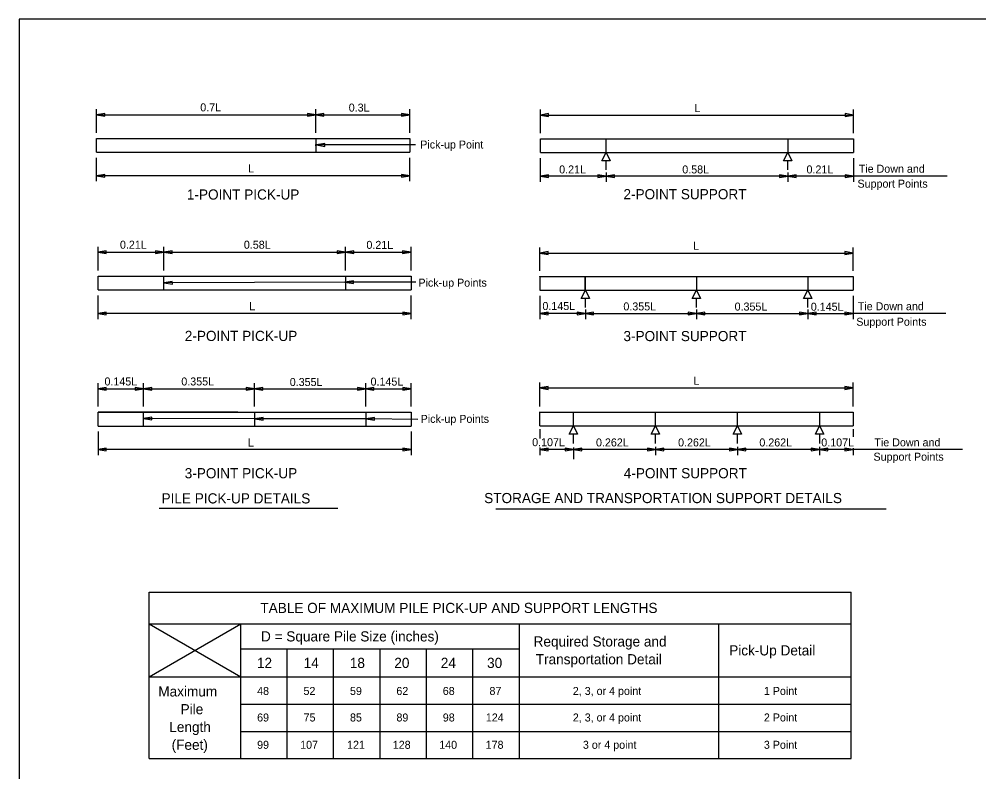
# Model space of a CAD drawing. Extents: x 112309.5 to 112344.2, y 111905.2 to 111923.
# Drawn here: x 112309.53 to 112321.62, y 111912.5 to 111921.98 of the extents above; entities that cross this region are included whole.
import ezdxf

# ---------------------------------------------------------------- set-up
doc = ezdxf.new("R2010")
doc.units = 0
for name, color, linetype in [('ActivePts-ConstElements', 7, 'Continuous'), ('AdhocPoint_dp', 7, 'Continuous'), ('PlotBorder_dp', 7, 'Continuous'), ('TextMisc', 7, 'Continuous')]:
    doc.layers.add(name, color=color, linetype=linetype)

msp = doc.modelspace()

# ---------------------------------------------------------------- linework, layer by layer
at = {"layer": 'ActivePts-ConstElements'}
msp.add_lwpolyline([(112309.535, 111909.004), (112330.06, 111909.004), (112330.06, 111921.977), (112309.535, 111921.977)], close=True, dxfattribs=at)
at = {"layer": 'AdhocPoint_dp'}
for p, q in [((112310.509, 111920.544), (112310.509, 111920.844)), ((112313.27, 111920.544), (112313.27, 111920.844)), ((112314.454, 111920.544), (112314.454, 111920.844)), ((112316.1, 111920.542), (112316.1, 111920.839)), ((112320.045, 111920.542), (112320.045, 111920.839)), ((112310.509, 111920.774), (112313.27, 111920.774)), ((112313.27, 111920.774), (112314.454, 111920.774)), ((112316.1, 111920.769), (112320.045, 111920.769)), ((112314.529, 111920.393), (112313.279, 111920.393)), ((112310.509, 111919.935), (112310.509, 111920.229)), ((112314.454, 111919.935), (112314.454, 111920.23)), ((112316.1, 111919.93), (112316.1, 111920.228)), ((112316.929, 111920.078), (112316.929, 111920.194)), ((112319.218, 111920.078), (112319.218, 111920.194)), ((112320.045, 111920.228), (112320.045, 111919.93)), ((112314.454, 111920.005), (112310.509, 111920.005)), ((112316.929, 111920), (112316.1, 111920)), ((112316.929, 111920.045), (112316.929, 111919.93)), ((112319.217, 111920), (112316.929, 111920)), ((112319.217, 111920.044), (112319.217, 111919.93)), ((112320.045, 111920), (112319.217, 111920)), ((112321.226, 111920), (112320.045, 111920)), ((112310.528, 111918.812), (112310.528, 111919.111)), ((112311.356, 111918.812), (112311.356, 111919.111)), ((112313.644, 111918.812), (112313.644, 111919.111)), ((112314.473, 111918.812), (112314.473, 111919.111)), ((112316.095, 111918.808), (112316.095, 111919.102)), ((112320.039, 111918.808), (112320.039, 111919.102)), ((112310.528, 111919.041), (112311.356, 111919.041)), ((112311.356, 111919.041), (112313.644, 111919.041)), ((112313.644, 111919.041), (112314.469, 111919.041)), ((112316.095, 111919.032), (112320.039, 111919.032)), ((112316.095, 111918.738), (112316.095, 111918.742)), ((112316.666, 111918.738), (112316.666, 111918.74)), ((112318.067, 111918.738), (112318.067, 111918.741)), ((112313.639, 111918.665), (112311.359, 111918.657)), ((112314.532, 111918.665), (112313.639, 111918.665)), ((112310.528, 111918.2), (112310.528, 111918.497)), ((112314.473, 111918.2), (112314.473, 111918.497)), ((112316.095, 111918.494), (112316.095, 111918.2)), ((112320.039, 111918.494), (112320.039, 111918.2)), ((112316.668, 111918.344), (112316.668, 111918.46)), ((112318.068, 111918.344), (112318.068, 111918.46)), ((112319.469, 111918.344), (112319.469, 111918.46)), ((112314.473, 111918.27), (112310.528, 111918.27)), ((112316.667, 111918.27), (112316.095, 111918.27)), ((112316.667, 111918.321), (112316.667, 111918.2)), ((112316.667, 111918.27), (112318.069, 111918.27)), ((112318.069, 111918.321), (112318.069, 111918.2)), ((112318.069, 111918.27), (112319.469, 111918.27)), ((112319.469, 111918.321), (112319.469, 111918.2)), ((112319.469, 111918.27), (112320.039, 111918.27)), ((112321.206, 111918.27), (112320.039, 111918.27)), ((112316.095, 111917.099), (112316.095, 111917.403)), ((112320.039, 111917.099), (112320.039, 111917.403)), ((112310.528, 111917.097), (112310.528, 111917.392)), ((112310.528, 111917.322), (112311.099, 111917.322)), ((112311.099, 111917.097), (112311.099, 111917.392)), ((112311.099, 111917.322), (112312.5, 111917.322)), ((112312.5, 111917.097), (112312.5, 111917.392)), ((112312.5, 111917.322), (112313.9, 111917.322)), ((112313.9, 111917.097), (112313.9, 111917.392)), ((112313.9, 111917.322), (112314.473, 111917.322)), ((112314.473, 111917.097), (112314.473, 111917.392)), ((112316.095, 111917.333), (112320.039, 111917.333)), ((112316.095, 111917.029), (112316.095, 111917.033)), ((112312.504, 111916.945), (112311.1, 111916.948)), ((112313.907, 111916.945), (112312.504, 111916.945)), ((112314.556, 111916.936), (112313.907, 111916.945)), ((112316.666, 111917.029), (112316.666, 111917.031)), ((112318.067, 111917.029), (112318.067, 111917.032)), ((112316.095, 111916.815), (112316.095, 111916.695)), ((112320.039, 111916.815), (112320.039, 111916.716)), ((112310.528, 111916.783), (112310.528, 111916.487)), ((112314.473, 111916.783), (112314.473, 111916.487)), ((112316.518, 111916.635), (112316.518, 111916.751)), ((112317.551, 111916.635), (112317.551, 111916.751)), ((112318.584, 111916.635), (112318.584, 111916.751)), ((112319.619, 111916.635), (112319.619, 111916.751)), ((112314.473, 111916.557), (112310.528, 111916.557)), ((112316.095, 111916.583), (112316.095, 111916.487)), ((112316.518, 111916.557), (112316.095, 111916.557)), ((112316.517, 111916.584), (112316.517, 111916.437)), ((112317.552, 111916.557), (112316.518, 111916.557)), ((112317.55, 111916.591), (112317.55, 111916.487)), ((112318.585, 111916.557), (112317.552, 111916.557)), ((112318.584, 111916.591), (112318.584, 111916.487)), ((112319.617, 111916.557), (112318.585, 111916.557)), ((112319.617, 111916.59), (112319.617, 111916.487)), ((112320.038, 111916.557), (112319.617, 111916.557)), ((112321.418, 111916.557), (112320.038, 111916.557)), ((112320.039, 111916.576), (112320.039, 111916.487)), ((112316.517, 111916.519), (112316.517, 111916.487)), ((112318.585, 111916.487), (112318.585, 111916.487)), ((112313.55, 111915.814), (112311.298, 111915.814)), ((112315.539, 111915.811), (112320.458, 111915.811)), ((112311.172, 111912.666), (112311.172, 111914.762)), ((112311.172, 111914.762), (112320.016, 111914.762)), ((112320.016, 111912.666), (112320.016, 111914.762)), ((112311.172, 111914.362), (112320.016, 111914.362)), ((112311.172, 111913.695), (112312.327, 111914.362)), ((112311.172, 111914.362), (112312.327, 111913.695)), ((112312.327, 111912.666), (112312.327, 111914.362)), ((112315.836, 111912.666), (112315.836, 111914.362)), ((112318.349, 111912.666), (112318.349, 111914.362)), ((112312.327, 111914.045), (112315.836, 111914.045)), ((112312.911, 111912.666), (112312.911, 111914.045)), ((112313.496, 111912.666), (112313.496, 111914.045)), ((112314.081, 111912.666), (112314.081, 111914.045)), ((112314.666, 111912.666), (112314.666, 111914.045)), ((112315.251, 111912.666), (112315.251, 111914.045)), ((112311.172, 111913.695), (112320.016, 111913.695)), ((112312.327, 111913.35), (112320.016, 111913.35)), ((112312.327, 111913.005), (112320.016, 111913.005)), ((112311.172, 111912.666), (112320.016, 111912.666))]:
    msp.add_line(p, q, dxfattribs=at)
for points in [[(112310.509, 111920.774), (112310.614, 111920.756), (112310.614, 111920.791)], [(112313.27, 111920.774), (112313.166, 111920.791), (112313.166, 111920.756)], [(112313.27, 111920.774), (112313.374, 111920.756), (112313.374, 111920.791)], [(112314.454, 111920.774), (112314.35, 111920.791), (112314.35, 111920.756)], [(112316.1, 111920.769), (112316.204, 111920.751), (112316.204, 111920.787)], [(112320.045, 111920.769), (112319.941, 111920.787), (112319.941, 111920.751)], [(112313.264, 111920.392), (112313.282, 111920.389), (112313.282, 111920.395)], [(112313.279, 111920.393), (112313.383, 111920.375), (112313.383, 111920.411)], [(112316.929, 111920.298), (112316.981, 111920.194), (112316.876, 111920.194)], [(112319.217, 111920.298), (112319.269, 111920.194), (112319.164, 111920.194)], [(112310.509, 111920.005), (112310.614, 111919.987), (112310.614, 111920.022)], [(112314.454, 111920.005), (112314.349, 111920.022), (112314.349, 111919.987)], [(112316.1, 111920), (112316.204, 111919.982), (112316.204, 111920.018)], [(112316.929, 111920), (112316.824, 111920.018), (112316.824, 111919.982)], [(112316.929, 111920), (112317.033, 111919.982), (112317.033, 111920.018)], [(112319.217, 111920), (112319.113, 111920.018), (112319.113, 111919.982)], [(112319.217, 111920), (112319.321, 111919.982), (112319.321, 111920.018)], [(112320.045, 111920), (112319.941, 111920.018), (112319.941, 111919.982)], [(112310.528, 111919.041), (112310.632, 111919.024), (112310.632, 111919.059)], [(112311.356, 111919.041), (112311.252, 111919.059), (112311.252, 111919.024)], [(112311.356, 111919.041), (112311.46, 111919.024), (112311.46, 111919.059)], [(112313.644, 111919.041), (112313.54, 111919.059), (112313.54, 111919.024)], [(112313.644, 111919.041), (112313.749, 111919.024), (112313.749, 111919.059)], [(112314.469, 111919.041), (112314.364, 111919.059), (112314.364, 111919.024)], [(112316.095, 111919.032), (112316.199, 111919.014), (112316.199, 111919.05)], [(112320.039, 111919.032), (112319.935, 111919.05), (112319.935, 111919.014)], [(112311.359, 111918.657), (112311.464, 111918.639), (112311.463, 111918.675)], [(112313.639, 111918.665), (112313.744, 111918.647), (112313.744, 111918.683)], [(112316.667, 111918.564), (112316.719, 111918.46), (112316.614, 111918.46)], [(112318.067, 111918.564), (112318.119, 111918.46), (112318.014, 111918.46)], [(112319.468, 111918.564), (112319.52, 111918.46), (112319.415, 111918.46)], [(112310.528, 111918.27), (112310.632, 111918.252), (112310.632, 111918.287)], [(112314.473, 111918.27), (112314.369, 111918.287), (112314.369, 111918.252)], [(112316.095, 111918.27), (112316.199, 111918.252), (112316.199, 111918.287)], [(112316.667, 111918.27), (112316.563, 111918.287), (112316.563, 111918.252)], [(112316.667, 111918.27), (112316.771, 111918.252), (112316.771, 111918.287)], [(112318.069, 111918.27), (112317.964, 111918.287), (112317.964, 111918.252)], [(112318.069, 111918.27), (112318.173, 111918.252), (112318.173, 111918.287)], [(112319.469, 111918.27), (112319.365, 111918.287), (112319.365, 111918.252)], [(112319.469, 111918.27), (112319.574, 111918.252), (112319.574, 111918.287)], [(112320.039, 111918.27), (112319.935, 111918.287), (112319.935, 111918.252)], [(112310.528, 111917.322), (112310.632, 111917.304), (112310.632, 111917.34)], [(112311.099, 111917.322), (112310.995, 111917.34), (112310.995, 111917.304)], [(112311.099, 111917.322), (112311.204, 111917.304), (112311.204, 111917.34)], [(112312.5, 111917.322), (112312.396, 111917.34), (112312.396, 111917.304)], [(112312.5, 111917.322), (112312.604, 111917.304), (112312.604, 111917.34)], [(112313.9, 111917.322), (112313.796, 111917.34), (112313.796, 111917.304)], [(112313.9, 111917.322), (112314.004, 111917.304), (112314.004, 111917.34)], [(112314.473, 111917.322), (112314.369, 111917.34), (112314.369, 111917.304)], [(112316.095, 111917.333), (112316.199, 111917.315), (112316.199, 111917.35)], [(112320.039, 111917.333), (112319.935, 111917.35), (112319.935, 111917.315)], [(112311.1, 111916.948), (112311.204, 111916.93), (112311.204, 111916.965)], [(112312.504, 111916.945), (112312.608, 111916.927), (112312.608, 111916.962)], [(112313.907, 111916.945), (112314.011, 111916.926), (112314.011, 111916.961)], [(112316.517, 111916.855), (112316.569, 111916.751), (112316.464, 111916.751)], [(112317.55, 111916.855), (112317.603, 111916.751), (112317.498, 111916.751)], [(112318.584, 111916.855), (112318.636, 111916.751), (112318.531, 111916.751)], [(112319.618, 111916.855), (112319.67, 111916.751), (112319.565, 111916.751)], [(112310.528, 111916.557), (112310.632, 111916.539), (112310.632, 111916.574)], [(112314.473, 111916.557), (112314.369, 111916.574), (112314.369, 111916.539)], [(112316.095, 111916.557), (112316.199, 111916.539), (112316.199, 111916.574)], [(112316.518, 111916.557), (112316.414, 111916.574), (112316.414, 111916.539)], [(112316.518, 111916.557), (112316.622, 111916.539), (112316.622, 111916.574)], [(112317.552, 111916.557), (112317.448, 111916.574), (112317.448, 111916.539)], [(112317.552, 111916.557), (112317.656, 111916.539), (112317.656, 111916.574)], [(112318.585, 111916.557), (112318.481, 111916.574), (112318.481, 111916.539)], [(112318.585, 111916.557), (112318.689, 111916.539), (112318.689, 111916.574)], [(112319.617, 111916.557), (112319.513, 111916.574), (112319.513, 111916.539)], [(112319.617, 111916.557), (112319.721, 111916.539), (112319.721, 111916.574)], [(112320.038, 111916.557), (112319.934, 111916.574), (112319.934, 111916.539)]]:
    msp.add_lwpolyline(points, close=True, dxfattribs=at)
at = {"layer": 'PlotBorder_dp'}
for p, q in [((112310.509, 111920.474), (112314.454, 111920.474)), ((112310.509, 111920.3), (112310.509, 111920.474)), ((112313.27, 111920.474), (112313.27, 111920.3)), ((112314.454, 111920.474), (112314.454, 111920.3)), ((112316.1, 111920.472), (112320.045, 111920.472)), ((112316.1, 111920.298), (112316.1, 111920.472)), ((112316.929, 111920.298), (112316.929, 111920.472)), ((112319.217, 111920.472), (112319.217, 111920.298)), ((112320.045, 111920.472), (112320.045, 111920.298)), ((112310.509, 111920.3), (112314.454, 111920.3)), ((112316.1, 111920.298), (112320.045, 111920.298)), ((112310.528, 111918.742), (112314.473, 111918.742)), ((112310.528, 111918.568), (112310.528, 111918.742)), ((112311.356, 111918.568), (112311.356, 111918.742)), ((112313.644, 111918.742), (112313.644, 111918.568)), ((112314.473, 111918.742), (112314.473, 111918.568)), ((112316.095, 111918.738), (112320.039, 111918.738)), ((112316.095, 111918.738), (112316.095, 111918.564)), ((112316.666, 111918.564), (112316.666, 111918.738)), ((112316.667, 111918.564), (112316.667, 111918.738)), ((112318.067, 111918.738), (112318.067, 111918.564)), ((112318.141, 111918.738), (112320.039, 111918.738)), ((112319.468, 111918.738), (112319.468, 111918.564)), ((112320.039, 111918.738), (112320.039, 111918.564)), ((112310.528, 111918.568), (112314.473, 111918.568)), ((112316.095, 111918.564), (112320.039, 111918.564)), ((112310.528, 111917.027), (112314.473, 111917.027)), ((112312.287, 111917.027), (112310.528, 111917.027)), ((112310.528, 111916.853), (112310.528, 111917.027)), ((112311.099, 111916.853), (112311.099, 111917.027)), ((112312.5, 111917.027), (112312.5, 111916.853)), ((112313.9, 111917.027), (112313.9, 111916.853)), ((112314.473, 111917.027), (112314.473, 111916.853)), ((112316.095, 111917.029), (112320.039, 111917.029)), ((112316.095, 111916.855), (112316.095, 111917.029)), ((112316.517, 111916.855), (112316.517, 111917.029)), ((112317.55, 111916.855), (112317.55, 111917.029)), ((112318.141, 111917.029), (112320.039, 111917.029)), ((112318.584, 111916.855), (112318.584, 111917.029)), ((112319.618, 111917.029), (112319.618, 111916.855)), ((112320.039, 111917.029), (112320.039, 111916.855)), ((112310.528, 111916.853), (112314.473, 111916.853)), ((112316.095, 111916.855), (112320.039, 111916.855))]:
    msp.add_line(p, q, dxfattribs=at)

# ---------------------------------------------------------------- texts
at = {"layer": 'AdhocPoint_dp'}
for s, p in [('Required Storage and', (112316.015, 111914.076)), ('Transportation Detail  ', (112316.042, 111913.852)), ('Maximum', (112311.287, 111913.447)), ('Pile', (112311.568, 111913.223)), ('Length', (112311.426, 111912.999)), ('(Feet)', (112311.455, 111912.775))]:
    msp.add_text(s, height=0.128, dxfattribs=at).set_placement(p)
at = {"layer": 'TextMisc'}
for s, height, p in [('0.7L', 0.1008, (112311.816, 111920.816)), ('0.3L', 0.1008, (112313.686, 111920.813)), ('L', 0.101, (112318.04, 111920.807)), ('Pick-up Point', 0.1008, (112314.587, 111920.348)), ('L', 0.101, (112312.418, 111920.047)), ('0.21L', 0.1008, (112316.337, 111920.034)), ('0.58L', 0.1008, (112317.888, 111920.034)), ('0.21L', 0.1008, (112319.453, 111920.034)), ('Tie Down and', 0.1008, (112320.111, 111920.043)), ('Support Points', 0.1008, (112320.095, 111919.855)), ('1-POINT PICK-UP', 0.128, (112311.647, 111919.705)), ('2-POINT SUPPORT', 0.128, (112317.147, 111919.709)), ('0.21L', 0.1008, (112310.804, 111919.086)), ('0.58L', 0.1008, (112312.365, 111919.086)), ('0.21L', 0.1008, (112313.909, 111919.084)), ('L', 0.101, (112318.025, 111919.072)), ('Pick-up Points', 0.1008, (112314.564, 111918.608)), ('L', 0.101, (112312.433, 111918.312)), ('0.145L', 0.1008, (112316.126, 111918.314)), ('0.355L', 0.1008, (112317.146, 111918.309)), ('0.355L', 0.1008, (112318.547, 111918.307)), ('0.145L', 0.1008, (112319.507, 111918.305)), ('Tie Down and', 0.1008, (112320.099, 111918.311)), ('Support Points', 0.1008, (112320.08, 111918.116)), ('2-POINT PICK-UP', 0.128, (112311.621, 111917.924)), ('3-POINT SUPPORT', 0.128, (112317.147, 111917.922)), ('0.145L', 0.1008, (112310.609, 111917.364)), ('0.355L', 0.1008, (112311.577, 111917.364)), ('0.355L', 0.1008, (112312.943, 111917.357)), ('0.145L', 0.1008, (112313.961, 111917.362)), ('L', 0.101, (112318.03, 111917.372)), ('Pick-up Points', 0.1008, (112314.592, 111916.893)), ('L', 0.101, (112312.416, 111916.595)), ('0.107L', 0.1008, (112315.997, 111916.599)), ('0.262L', 0.1008, (112316.801, 111916.596)), ('0.262L', 0.1008, (112317.835, 111916.596)), ('0.262L', 0.1008, (112318.859, 111916.596)), ('0.107L', 0.1008, (112319.639, 111916.596)), ('Tie Down and', 0.1008, (112320.308, 111916.597)), ('Support Points', 0.1008, (112320.297, 111916.416)), ('3-POINT PICK-UP', 0.128, (112311.62, 111916.195)), ('4-POINT SUPPORT', 0.128, (112317.151, 111916.195)), ('PILE PICK-UP DETAILS', 0.128, (112311.328, 111915.878)), ('STORAGE AND TRANSPORTATION SUPPORT DETAILS', 0.128, (112315.392, 111915.882)), ('TABLE OF MAXIMUM PILE PICK-UP AND SUPPORT LENGTHS', 0.128, (112312.573, 111914.498)), ('D = Square Pile Size (inches)', 0.128, (112312.581, 111914.14)), ('Pick-Up Detail', 0.128, (112318.479, 111913.964)), ('12', 0.128, (112312.53, 111913.806)), ('14', 0.128, (112313.118, 111913.806)), ('18', 0.128, (112313.7, 111913.806)), ('20', 0.128, (112314.26, 111913.806)), ('24', 0.128, (112314.846, 111913.806)), ('30', 0.128, (112315.429, 111913.806)), ('48', 0.1008, (112312.532, 111913.466)), ('52', 0.1008, (112313.116, 111913.466)), ('59', 0.1008, (112313.702, 111913.466)), ('62', 0.1008, (112314.286, 111913.466)), ('68', 0.1008, (112314.871, 111913.466)), ('87', 0.1008, (112315.459, 111913.466)), ('2, 3, or 4 point', 0.1008, (112316.509, 111913.466)), ('1 Point', 0.1008, (112318.916, 111913.466)), ('69', 0.1008, (112312.532, 111913.132)), ('75', 0.1008, (112313.117, 111913.132)), ('85', 0.1008, (112313.702, 111913.132)), ('89', 0.1008, (112314.287, 111913.132)), ('98', 0.1008, (112314.871, 111913.132)), ('124', 0.1008, (112315.413, 111913.132)), ('2, 3, or 4 point', 0.1008, (112316.509, 111913.132)), ('2 Point', 0.1008, (112318.916, 111913.132)), ('99', 0.1008, (112312.532, 111912.788)), ('107', 0.1008, (112313.074, 111912.788)), ('121', 0.1008, (112313.665, 111912.788)), ('128', 0.1008, (112314.241, 111912.788)), ('140', 0.1008, (112314.826, 111912.788)), ('178', 0.1008, (112315.411, 111912.788)), ('3 or 4 point', 0.1008, (112316.636, 111912.788)), ('3 Point', 0.1008, (112318.916, 111912.788))]:
    msp.add_text(s, height=height, dxfattribs=at).set_placement(p)

doc.saveas('drawing.dxf')
